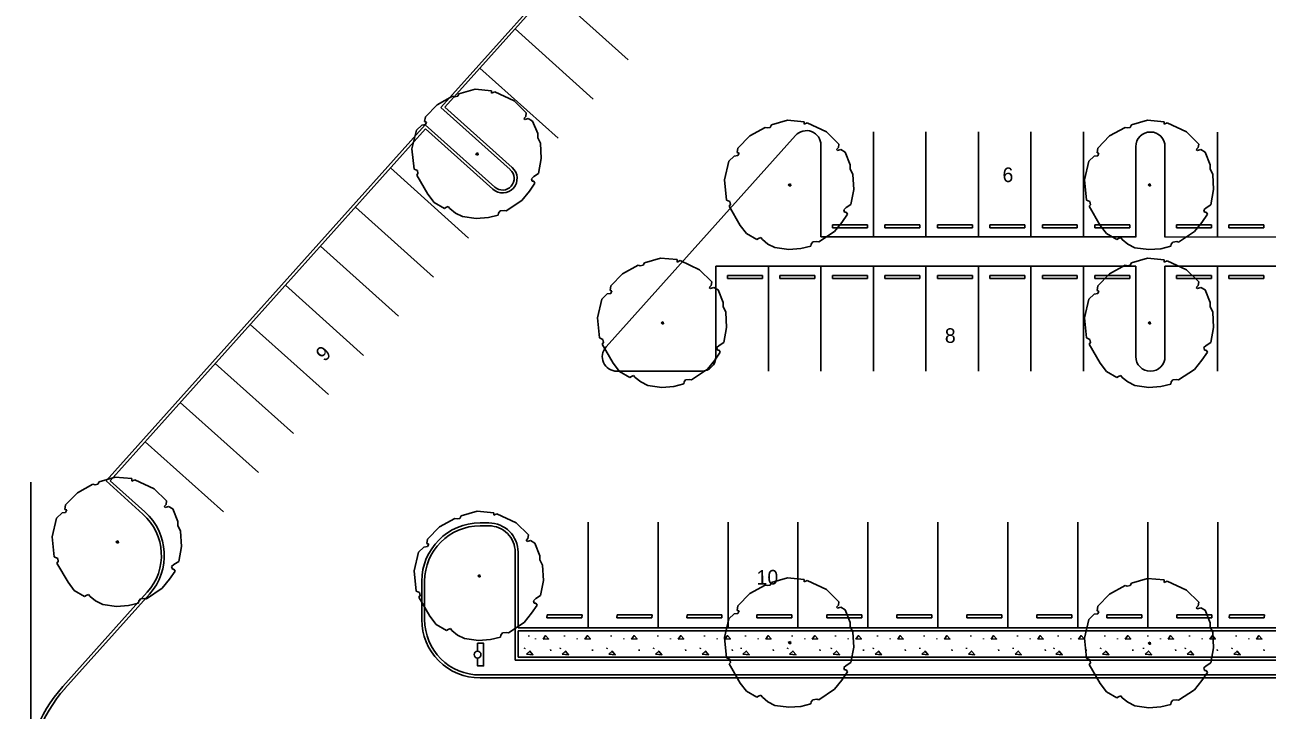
# Model space of a CAD drawing. Extents: x 6712138 to 6712574, y 1869536 to 1870160.
# Drawn here: x 6712157.5 to 6712370.5, y 1869919.6 to 1870037 of the extents above; entities that cross this region are included whole.
import ezdxf

# ---------------------------------------------------------------- set-up
doc = ezdxf.new("R2010")
doc.units = 0
for name, color, linetype in [('A-ANNO-TEXT', 7, 'Continuous'), ('A-FLOR-PATT', 7, 'Continuous'), ('C-Boun-Imaginary', 7, 'Continuous'), ('C-PRKG-CONC', 7, 'Continuous'), ('C-SIGN-PARKING', 7, 'Continuous'), ('L-tree', 7, 'Continuous')]:
    doc.layers.add(name, color=color, linetype=linetype)

# ---------------------------------------------------------------- blocks, each defined once
blk = doc.blocks.new('TREE 1')
at = {"layer": 'L-tree'}
for p, q in [((-0.027, 0.572), (-0.168, 0.532)), ((0.117, 0.559), (-0.027, 0.572)), ((0.117, 0.537), (0.117, 0.559)), ((0.144, 0.55), (0.117, 0.537)), ((0.312, 0.471), (0.144, 0.55)), ((-0.357, 0.436), (-0.46, 0.33)), ((-0.223, 0.51), (-0.357, 0.436)), ((-0.203, 0.506), (-0.223, 0.51)), ((-0.178, 0.51), (-0.203, 0.506)), ((-0.168, 0.532), (-0.178, 0.51)), ((0.419, 0.365), (0.312, 0.471)), ((-0.46, 0.33), (-0.467, 0.29)), ((0.398, 0.317), (0.415, 0.334)), ((0.415, 0.334), (0.419, 0.365)), ((-0.491, 0.26), (-0.539, 0.216)), ((-0.46, 0.264), (-0.491, 0.26)), ((-0.467, 0.29), (-0.45, 0.286)), ((-0.45, 0.286), (-0.46, 0.264)), ((0.408, 0.308), (0.398, 0.317)), ((0.436, 0.317), (0.408, 0.308)), ((0.474, 0.295), (0.436, 0.317)), ((0.518, 0.185), (0.474, 0.295)), ((-0.539, 0.216), (-0.577, 0.053)), ((0.518, 0.15), (0.518, 0.185)), ((0.542, 0.101), (0.518, 0.15)), ((-0.577, 0.053), (-0.559, -0.123)), ((-0.003, 0.018), (-0.021, 0.009)), ((-0.021, 0.009), (-0.014, 0)), ((-0.014, 0), (0, 0)), ((0, 0), (-0.003, 0.018)), ((0.549, -0.031), (0.542, 0.101)), ((0.525, -0.163), (0.549, -0.031)), ((-0.559, -0.123), (-0.529, -0.136)), ((-0.525, -0.163), (-0.535, -0.176)), ((-0.535, -0.176), (-0.439, -0.343)), ((-0.529, -0.136), (-0.525, -0.163)), ((0.463, -0.207), (0.484, -0.189)), ((0.47, -0.229), (0.463, -0.207)), ((0.484, -0.189), (0.525, -0.163)), ((0.381, -0.396), (0.446, -0.317)), ((0.446, -0.317), (0.494, -0.246)), ((0.484, -0.229), (0.47, -0.229)), ((0.494, -0.246), (0.484, -0.229)), ((-0.439, -0.343), (-0.384, -0.414)), ((-0.384, -0.414), (-0.295, -0.466)), ((0.244, -0.488), (0.381, -0.396)), ((-0.295, -0.466), (-0.281, -0.458)), ((-0.281, -0.458), (-0.261, -0.449)), ((-0.261, -0.449), (-0.247, -0.466)), ((-0.247, -0.466), (-0.199, -0.506)), ((-0.199, -0.506), (-0.137, -0.537)), ((-0.137, -0.537), (-0.017, -0.554)), ((0.089, -0.546), (0.175, -0.524)), ((0.175, -0.524), (0.178, -0.506)), ((0.178, -0.506), (0.192, -0.488)), ((0.192, -0.488), (0.227, -0.484)), ((0.227, -0.484), (0.244, -0.488)), ((-0.017, -0.554), (0.089, -0.546))]:
    blk.add_line(p, q, dxfattribs=at)

msp = doc.modelspace()

# ---------------------------------------------------------------- linework, layer by layer
at = {"layer": 'A-FLOR-PATT'}
for p, q in [((6712243.93, 1869932.21), (6712243.93, 1869932.37)), ((6712245.05, 1869931.74), (6712245.05, 1869931.85)), ((6712250.04, 1869932.21), (6712250.04, 1869932.37)), ((6712252.21, 1869931.74), (6712252.21, 1869931.85)), ((6712258.04, 1869932.21), (6712258.04, 1869932.37)), ((6712260.21, 1869931.74), (6712260.21, 1869931.85)), ((6712266.04, 1869932.21), (6712266.04, 1869932.37)), ((6712268.21, 1869931.74), (6712268.21, 1869931.85)), ((6712274.04, 1869932.21), (6712274.04, 1869932.37)), ((6712276.21, 1869931.74), (6712276.21, 1869931.85)), ((6712281.04, 1869932.21), (6712281.04, 1869932.37)), ((6712283.21, 1869931.74), (6712283.21, 1869931.85)), ((6712289.04, 1869932.21), (6712289.04, 1869932.37)), ((6712291.21, 1869931.74), (6712291.21, 1869931.85)), ((6712296.52, 1869932.21), (6712296.52, 1869932.37)), ((6712298.69, 1869931.74), (6712298.69, 1869931.85)), ((6712303.69, 1869932.21), (6712303.69, 1869932.37)), ((6712305.86, 1869931.74), (6712305.86, 1869931.85)), ((6712311.69, 1869932.21), (6712311.69, 1869932.37)), ((6712313.86, 1869931.74), (6712313.86, 1869931.85)), ((6712319.69, 1869932.21), (6712319.69, 1869932.37)), ((6712321.86, 1869931.74), (6712321.86, 1869931.85)), ((6712327.69, 1869932.21), (6712327.69, 1869932.37)), ((6712329.86, 1869931.74), (6712329.86, 1869931.85)), ((6712334.69, 1869932.21), (6712334.69, 1869932.37)), ((6712336.86, 1869931.74), (6712336.86, 1869931.85)), ((6712342.69, 1869932.21), (6712342.69, 1869932.37)), ((6712344.86, 1869931.74), (6712344.86, 1869931.85)), ((6712350.04, 1869932.21), (6712350.04, 1869932.37)), ((6712352.21, 1869931.74), (6712352.21, 1869931.85)), ((6712357.2, 1869932.21), (6712357.2, 1869932.37)), ((6712359.37, 1869931.74), (6712359.37, 1869931.85)), ((6712365.2, 1869932.21), (6712365.2, 1869932.37)), ((6712367.37, 1869931.74), (6712367.37, 1869931.85)), ((6712243.18, 1869930.12), (6712243.22, 1869930.24)), ((6712247.68, 1869929.77), (6712247.64, 1869929.97)), ((6712249.29, 1869930.12), (6712249.33, 1869930.24)), ((6712254.84, 1869929.77), (6712254.8, 1869929.97)), ((6712257.29, 1869930.12), (6712257.33, 1869930.24)), ((6712262.84, 1869929.77), (6712262.8, 1869929.97)), ((6712265.29, 1869930.12), (6712265.33, 1869930.24)), ((6712270.84, 1869929.77), (6712270.8, 1869929.97)), ((6712273.29, 1869930.12), (6712273.33, 1869930.24)), ((6712278.84, 1869929.77), (6712278.8, 1869929.97)), ((6712280.29, 1869930.12), (6712280.33, 1869930.24)), ((6712285.84, 1869929.77), (6712285.8, 1869929.97)), ((6712288.29, 1869930.12), (6712288.33, 1869930.24)), ((6712293.84, 1869929.77), (6712293.8, 1869929.97)), ((6712295.77, 1869930.12), (6712295.81, 1869930.24)), ((6712301.32, 1869929.77), (6712301.28, 1869929.97)), ((6712302.94, 1869930.12), (6712302.98, 1869930.24)), ((6712308.49, 1869929.77), (6712308.45, 1869929.97)), ((6712310.94, 1869930.12), (6712310.98, 1869930.24)), ((6712316.49, 1869929.77), (6712316.45, 1869929.97)), ((6712318.94, 1869930.12), (6712318.98, 1869930.24)), ((6712324.49, 1869929.77), (6712324.45, 1869929.97)), ((6712326.94, 1869930.12), (6712326.98, 1869930.24)), ((6712332.49, 1869929.77), (6712332.45, 1869929.97)), ((6712333.94, 1869930.12), (6712333.98, 1869930.24)), ((6712339.49, 1869929.77), (6712339.45, 1869929.97)), ((6712341.94, 1869930.12), (6712341.98, 1869930.24)), ((6712347.49, 1869929.77), (6712347.45, 1869929.97)), ((6712349.29, 1869930.12), (6712349.33, 1869930.24)), ((6712354.84, 1869929.77), (6712354.8, 1869929.97)), ((6712356.45, 1869930.12), (6712356.49, 1869930.24)), ((6712362, 1869929.77), (6712361.96, 1869929.97)), ((6712364.45, 1869930.12), (6712364.49, 1869930.24)), ((6712370, 1869929.77), (6712369.96, 1869929.97))]:
    msp.add_line(p, q, dxfattribs=at)
for points in [[(6712246.36, 1869931.74), (6712246.79, 1869932.37), (6712247.3, 1869931.78)], [(6712253.52, 1869931.74), (6712253.95, 1869932.37), (6712254.46, 1869931.78)], [(6712261.52, 1869931.74), (6712261.95, 1869932.37), (6712262.46, 1869931.78)], [(6712269.52, 1869931.74), (6712269.95, 1869932.37), (6712270.46, 1869931.78)], [(6712277.52, 1869931.74), (6712277.95, 1869932.37), (6712278.46, 1869931.78)], [(6712284.52, 1869931.74), (6712284.95, 1869932.37), (6712285.46, 1869931.78)], [(6712292.52, 1869931.74), (6712292.95, 1869932.37), (6712293.46, 1869931.78)], [(6712300, 1869931.74), (6712300.43, 1869932.37), (6712300.94, 1869931.78)], [(6712307.17, 1869931.74), (6712307.6, 1869932.37), (6712308.11, 1869931.78)], [(6712315.17, 1869931.74), (6712315.6, 1869932.37), (6712316.11, 1869931.78)], [(6712323.17, 1869931.74), (6712323.6, 1869932.37), (6712324.11, 1869931.78)], [(6712331.17, 1869931.74), (6712331.6, 1869932.37), (6712332.11, 1869931.78)], [(6712338.17, 1869931.74), (6712338.6, 1869932.37), (6712339.11, 1869931.78)], [(6712346.17, 1869931.74), (6712346.6, 1869932.37), (6712347.11, 1869931.78)], [(6712353.52, 1869931.74), (6712353.95, 1869932.37), (6712354.46, 1869931.78)], [(6712360.68, 1869931.74), (6712361.11, 1869932.37), (6712361.62, 1869931.78)], [(6712368.68, 1869931.74), (6712369.11, 1869932.37), (6712369.62, 1869931.78)], [(6712243.52, 1869929.16), (6712244.08, 1869929.71), (6712244.62, 1869929.08)], [(6712249.63, 1869929.16), (6712250.19, 1869929.71), (6712250.73, 1869929.08)], [(6712257.63, 1869929.16), (6712258.19, 1869929.71), (6712258.73, 1869929.08)], [(6712265.63, 1869929.16), (6712266.19, 1869929.71), (6712266.73, 1869929.08)], [(6712273.63, 1869929.16), (6712274.19, 1869929.71), (6712274.73, 1869929.08)], [(6712280.63, 1869929.16), (6712281.19, 1869929.71), (6712281.73, 1869929.08)], [(6712288.63, 1869929.16), (6712289.19, 1869929.71), (6712289.73, 1869929.08)], [(6712296.11, 1869929.16), (6712296.67, 1869929.71), (6712297.21, 1869929.08)], [(6712303.28, 1869929.16), (6712303.84, 1869929.71), (6712304.38, 1869929.08)], [(6712311.28, 1869929.16), (6712311.84, 1869929.71), (6712312.38, 1869929.08)], [(6712319.28, 1869929.16), (6712319.84, 1869929.71), (6712320.38, 1869929.08)], [(6712327.28, 1869929.16), (6712327.84, 1869929.71), (6712328.38, 1869929.08)], [(6712334.28, 1869929.16), (6712334.84, 1869929.71), (6712335.38, 1869929.08)], [(6712342.28, 1869929.16), (6712342.84, 1869929.71), (6712343.38, 1869929.08)], [(6712349.62, 1869929.16), (6712350.18, 1869929.71), (6712350.72, 1869929.08)], [(6712356.79, 1869929.16), (6712357.35, 1869929.71), (6712357.89, 1869929.08)], [(6712364.79, 1869929.16), (6712365.35, 1869929.71), (6712365.89, 1869929.08)]]:
    msp.add_lwpolyline(points, close=True, dxfattribs=at)
at = {"layer": 'C-Boun-Imaginary'}
msp.add_lwpolyline([(6712158.49, 1869958.67), (6712158.49, 1869788.19), (6712188.82, 1869788.19)], dxfattribs=at)
at = {"layer": 'C-PRKG-CONC'}
for p, q in [((6712228.82, 1870022.9), (6712283.55, 1870083.96)), ((6712229.52, 1870022.94), (6712283.59, 1870083.26)), ((6712247.54, 1870043.05), (6712260.95, 1870031.03)), ((6712241.54, 1870036.34), (6712254.94, 1870024.33)), ((6712235.53, 1870029.64), (6712248.93, 1870017.63)), ((6712228.82, 1870022.9), (6712240.73, 1870012.22)), ((6712229.52, 1870022.94), (6712241.07, 1870012.59)), ((6712226.15, 1870019.92), (6712171.42, 1869958.86)), ((6712226.19, 1870019.22), (6712172.12, 1869958.9)), ((6712238.06, 1870009.24), (6712226.15, 1870019.92)), ((6712237.73, 1870008.87), (6712226.19, 1870019.22)), ((6712302.99, 1870000.68), (6712302.99, 1870018.68)), ((6712311.99, 1870000.68), (6712311.99, 1870018.68)), ((6712320.99, 1870000.68), (6712320.99, 1870018.68)), ((6712329.99, 1870000.68), (6712329.99, 1870018.68)), ((6712338.99, 1870000.68), (6712338.99, 1870018.68)), ((6712361.99, 1870000.67), (6712361.99, 1870018.67)), ((6712257.14, 1869981.84), (6712289.63, 1870018.08)), ((6712293.99, 1870016.41), (6712293.99, 1870000.68)), ((6712347.99, 1870016.17), (6712347.99, 1870000.67)), ((6712352.99, 1870016.17), (6712352.99, 1870000.67)), ((6712220.18, 1870012.51), (6712233.58, 1870000.5)), ((6712214.17, 1870005.81), (6712227.58, 1869993.8)), ((6712295.96, 1870002.26), (6712295.96, 1870002.76)), ((6712295.96, 1870002.76), (6712301.96, 1870002.76)), ((6712301.96, 1870002.26), (6712295.96, 1870002.26)), ((6712301.96, 1870002.76), (6712301.96, 1870002.26)), ((6712304.96, 1870002.26), (6712304.96, 1870002.76)), ((6712304.96, 1870002.76), (6712310.96, 1870002.76)), ((6712310.96, 1870002.26), (6712304.96, 1870002.26)), ((6712310.96, 1870002.76), (6712310.96, 1870002.26)), ((6712313.96, 1870002.26), (6712313.96, 1870002.76)), ((6712313.96, 1870002.76), (6712319.96, 1870002.76)), ((6712319.96, 1870002.26), (6712313.96, 1870002.26)), ((6712319.96, 1870002.76), (6712319.96, 1870002.26)), ((6712322.96, 1870002.26), (6712322.96, 1870002.76)), ((6712322.96, 1870002.76), (6712328.96, 1870002.76)), ((6712328.96, 1870002.26), (6712322.96, 1870002.26)), ((6712328.96, 1870002.76), (6712328.96, 1870002.26)), ((6712331.96, 1870002.26), (6712331.96, 1870002.76)), ((6712331.96, 1870002.76), (6712337.96, 1870002.76)), ((6712337.96, 1870002.26), (6712331.96, 1870002.26)), ((6712337.96, 1870002.76), (6712337.96, 1870002.26)), ((6712340.96, 1870002.26), (6712340.96, 1870002.76)), ((6712340.96, 1870002.76), (6712346.96, 1870002.76)), ((6712346.96, 1870002.26), (6712340.96, 1870002.26)), ((6712346.96, 1870002.76), (6712346.96, 1870002.26)), ((6712354.96, 1870002.26), (6712354.96, 1870002.76)), ((6712354.96, 1870002.76), (6712360.96, 1870002.76)), ((6712360.96, 1870002.26), (6712354.96, 1870002.26)), ((6712360.96, 1870002.76), (6712360.96, 1870002.26)), ((6712363.96, 1870002.26), (6712363.96, 1870002.76)), ((6712363.96, 1870002.76), (6712369.96, 1870002.76)), ((6712369.96, 1870002.26), (6712363.96, 1870002.26)), ((6712369.96, 1870002.76), (6712369.96, 1870002.26)), ((6712208.17, 1869999.11), (6712221.57, 1869987.1)), ((6712293.99, 1870000.68), (6712347.99, 1870000.68)), ((6712352.99, 1870000.68), (6712397.99, 1870000.67)), ((6712275.99, 1869995.68), (6712347.99, 1869995.67)), ((6712275.99, 1869980.17), (6712275.99, 1869995.68)), ((6712284.99, 1869995.67), (6712284.99, 1869977.67)), ((6712293.99, 1869995.67), (6712293.99, 1869977.67)), ((6712302.99, 1869995.67), (6712302.99, 1869977.67)), ((6712311.99, 1869995.67), (6712311.99, 1869977.67)), ((6712320.99, 1869995.67), (6712320.99, 1869977.67)), ((6712329.99, 1869995.67), (6712329.99, 1869977.67)), ((6712338.99, 1869995.67), (6712338.99, 1869977.67)), ((6712347.99, 1869980.17), (6712347.99, 1869995.67)), ((6712352.99, 1869995.67), (6712397.99, 1869995.67)), ((6712352.99, 1869980.17), (6712352.99, 1869995.67)), ((6712361.99, 1869995.67), (6712361.99, 1869977.67)), ((6712277.96, 1869994.09), (6712277.96, 1869993.59)), ((6712283.96, 1869994.09), (6712277.96, 1869994.09)), ((6712277.96, 1869993.59), (6712283.96, 1869993.59)), ((6712283.96, 1869993.59), (6712283.96, 1869994.09)), ((6712286.96, 1869994.09), (6712286.96, 1869993.59)), ((6712292.96, 1869994.09), (6712286.96, 1869994.09)), ((6712286.96, 1869993.59), (6712292.96, 1869993.59)), ((6712292.96, 1869993.59), (6712292.96, 1869994.09)), ((6712295.96, 1869994.09), (6712295.96, 1869993.59)), ((6712301.96, 1869994.09), (6712295.96, 1869994.09)), ((6712295.96, 1869993.59), (6712301.96, 1869993.59)), ((6712301.96, 1869993.59), (6712301.96, 1869994.09)), ((6712304.96, 1869994.09), (6712304.96, 1869993.59)), ((6712310.96, 1869994.09), (6712304.96, 1869994.09)), ((6712304.96, 1869993.59), (6712310.96, 1869993.59)), ((6712310.96, 1869993.59), (6712310.96, 1869994.09)), ((6712313.96, 1869994.09), (6712313.96, 1869993.59)), ((6712319.96, 1869994.09), (6712313.96, 1869994.09)), ((6712313.96, 1869993.59), (6712319.96, 1869993.59)), ((6712319.96, 1869993.59), (6712319.96, 1869994.09)), ((6712322.96, 1869994.09), (6712322.96, 1869993.59)), ((6712328.96, 1869994.09), (6712322.96, 1869994.09)), ((6712322.96, 1869993.59), (6712328.96, 1869993.59)), ((6712328.96, 1869993.59), (6712328.96, 1869994.09)), ((6712331.96, 1869994.09), (6712331.96, 1869993.59)), ((6712337.96, 1869994.09), (6712331.96, 1869994.09)), ((6712331.96, 1869993.59), (6712337.96, 1869993.59)), ((6712337.96, 1869993.59), (6712337.96, 1869994.09)), ((6712340.96, 1869994.09), (6712340.96, 1869993.59)), ((6712346.96, 1869994.09), (6712340.96, 1869994.09)), ((6712340.96, 1869993.59), (6712346.96, 1869993.59)), ((6712346.96, 1869993.59), (6712346.96, 1869994.09)), ((6712354.96, 1869994.09), (6712354.96, 1869993.59)), ((6712360.96, 1869994.09), (6712354.96, 1869994.09)), ((6712354.96, 1869993.59), (6712360.96, 1869993.59)), ((6712360.96, 1869993.59), (6712360.96, 1869994.09)), ((6712363.96, 1869994.09), (6712363.96, 1869993.59)), ((6712369.96, 1869994.09), (6712363.96, 1869994.09)), ((6712363.96, 1869993.59), (6712369.96, 1869993.59)), ((6712369.96, 1869993.59), (6712369.96, 1869994.09)), ((6712202.16, 1869992.41), (6712215.56, 1869980.39)), ((6712196.15, 1869985.71), (6712209.55, 1869973.69)), ((6712190.14, 1869979.01), (6712203.55, 1869966.99)), ((6712273.49, 1869977.67), (6712259.01, 1869977.67)), ((6712184.14, 1869972.3), (6712197.54, 1869960.29)), ((6712178.13, 1869965.6), (6712191.53, 1869953.59)), ((6712171.42, 1869958.86), (6712177.74, 1869953.19)), ((6712172.12, 1869958.9), (6712178.08, 1869953.56)), ((6712235.54, 1869951.67), (6712237.06, 1869951.67)), ((6712235.54, 1869951.17), (6712237.06, 1869951.17)), ((6712254.06, 1869951.82), (6712254.06, 1869933.82)), ((6712266.06, 1869951.82), (6712266.06, 1869933.82)), ((6712278.06, 1869951.82), (6712278.06, 1869933.82)), ((6712290.06, 1869951.82), (6712290.06, 1869933.82)), ((6712302.06, 1869951.82), (6712302.06, 1869933.82)), ((6712314.06, 1869951.82), (6712314.06, 1869933.82)), ((6712326.06, 1869951.82), (6712326.06, 1869933.82)), ((6712338.06, 1869951.82), (6712338.06, 1869933.82)), ((6712350.06, 1869951.82), (6712350.06, 1869933.82)), ((6712362.06, 1869951.82), (6712362.06, 1869933.82)), ((6712362.06, 1869951.82), (6712362.06, 1869933.82)), ((6712241.56, 1869946.67), (6712241.56, 1869928.17)), ((6712242.06, 1869946.67), (6712242.06, 1869933.67)), ((6712225.54, 1869941.67), (6712225.54, 1869935.11)), ((6712226.04, 1869941.67), (6712226.04, 1869935.11)), ((6712178.48, 1869939.78), (6712164, 1869923.62)), ((6712178.85, 1869939.44), (6712164.37, 1869923.29)), ((6712247.02, 1869935.41), (6712247.03, 1869935.91)), ((6712247.02, 1869935.41), (6712247.03, 1869935.91)), ((6712253.02, 1869935.41), (6712247.02, 1869935.41)), ((6712253.02, 1869935.41), (6712247.02, 1869935.41)), ((6712247.03, 1869935.91), (6712253.03, 1869935.91)), ((6712247.03, 1869935.91), (6712253.03, 1869935.91)), ((6712253.03, 1869935.91), (6712253.02, 1869935.41)), ((6712253.03, 1869935.91), (6712253.02, 1869935.41)), ((6712259.02, 1869935.41), (6712259.03, 1869935.91)), ((6712265.02, 1869935.41), (6712259.02, 1869935.41)), ((6712259.03, 1869935.91), (6712265.03, 1869935.91)), ((6712265.03, 1869935.91), (6712265.02, 1869935.41)), ((6712271.02, 1869935.41), (6712271.03, 1869935.91)), ((6712277.02, 1869935.41), (6712271.02, 1869935.41)), ((6712271.03, 1869935.91), (6712277.03, 1869935.91)), ((6712277.03, 1869935.91), (6712277.02, 1869935.41)), ((6712283.02, 1869935.41), (6712283.03, 1869935.91)), ((6712289.02, 1869935.41), (6712283.02, 1869935.41)), ((6712283.03, 1869935.91), (6712289.03, 1869935.91)), ((6712289.03, 1869935.91), (6712289.02, 1869935.41)), ((6712295.02, 1869935.41), (6712295.03, 1869935.91)), ((6712301.02, 1869935.41), (6712295.02, 1869935.41)), ((6712295.03, 1869935.91), (6712301.03, 1869935.91)), ((6712301.03, 1869935.91), (6712301.02, 1869935.41)), ((6712307.02, 1869935.41), (6712307.03, 1869935.91)), ((6712313.02, 1869935.41), (6712307.02, 1869935.41)), ((6712307.03, 1869935.91), (6712313.03, 1869935.91)), ((6712313.03, 1869935.91), (6712313.02, 1869935.41)), ((6712319.02, 1869935.41), (6712319.03, 1869935.91)), ((6712325.02, 1869935.41), (6712319.02, 1869935.41)), ((6712319.03, 1869935.91), (6712325.03, 1869935.91)), ((6712325.03, 1869935.91), (6712325.02, 1869935.41)), ((6712331.02, 1869935.41), (6712331.03, 1869935.91)), ((6712337.02, 1869935.41), (6712331.02, 1869935.41)), ((6712331.03, 1869935.91), (6712337.03, 1869935.91)), ((6712337.03, 1869935.91), (6712337.02, 1869935.41)), ((6712343.02, 1869935.41), (6712343.03, 1869935.91)), ((6712349.02, 1869935.41), (6712343.02, 1869935.41)), ((6712343.03, 1869935.91), (6712349.03, 1869935.91)), ((6712349.03, 1869935.91), (6712349.02, 1869935.41)), ((6712355.02, 1869935.41), (6712355.03, 1869935.91)), ((6712355.02, 1869935.41), (6712355.03, 1869935.91)), ((6712361.02, 1869935.41), (6712355.02, 1869935.41)), ((6712361.02, 1869935.41), (6712355.02, 1869935.41)), ((6712355.03, 1869935.91), (6712361.03, 1869935.91)), ((6712355.03, 1869935.91), (6712361.03, 1869935.91)), ((6712361.03, 1869935.91), (6712361.02, 1869935.41)), ((6712361.03, 1869935.91), (6712361.02, 1869935.41)), ((6712364.02, 1869935.41), (6712364.03, 1869935.91)), ((6712370.02, 1869935.41), (6712364.02, 1869935.41)), ((6712364.03, 1869935.91), (6712370.03, 1869935.91)), ((6712370.03, 1869935.91), (6712370.02, 1869935.41)), ((6712242.06, 1869933.67), (6712471.06, 1869933.67)), ((6712242.06, 1869933.17), (6712242.06, 1869928.67)), ((6712242.06, 1869933.17), (6712470.56, 1869933.17)), ((6712241.56, 1869928.17), (6712470.56, 1869928.17)), ((6712242.06, 1869928.67), (6712470.56, 1869928.67)), ((6712470.56, 1869925.61), (6712235.54, 1869925.61)), ((6712471.06, 1869925.11), (6712235.54, 1869925.11))]:
    msp.add_line(p, q, dxfattribs=at)
for centre, radius, start, end in [((6712291.49, 1870016.41), 2.5, 360, 138.1293), ((6712350.49, 1870016.17), 2.5, 0, 180), ((6712239.4, 1870010.73), 2.5, 228.1293, 48.1293), ((6712239.4, 1870010.73), 2, 228.1293, 48.1293), ((6712259.01, 1869980.17), 2.5, 138.1293, 270), ((6712273.49, 1869980.17), 2.5, 270, 360), ((6712350.49, 1869980.17), 2.5, 180, 360), ((6712171.4, 1869946.12), 9.5, 318.1293, 48.1293), ((6712171.4, 1869946.12), 10, 318.1293, 48.1293), ((6712235.54, 1869941.67), 10, 90, 180), ((6712235.54, 1869941.67), 9.5, 90, 180), ((6712237.06, 1869946.67), 5, 359.9997, 90.0093), ((6712237.06, 1869946.67), 4.5, 359.9997, 90.0093), ((6712235.54, 1869935.11), 10, 180, 270.0004), ((6712235.54, 1869935.11), 9.5, 180, 270.0004), ((6712182.99, 1869906.6), 25.5, 138.1293, 180), ((6712182.99, 1869906.6), 25, 138.1293, 180)]:
    msp.add_arc(centre, radius, start, end, dxfattribs=at)
at = {"layer": 'C-SIGN-PARKING'}
msp.add_lwpolyline([(6712235.11, 1869929.69), (6712235.11, 1869931.04), (6712236.14, 1869931.04), (6712236.14, 1869927.16), (6712235.11, 1869927.16), (6712235.11, 1869928.51)], dxfattribs=at)
msp.add_circle((6712235.11, 1869929.1), 0.586, dxfattribs=at)

# ---------------------------------------------------------------- block references
at = {"layer": 'L-tree', "xscale": 19.68503937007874, "yscale": 19.68503937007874}
for p in [(6712235.23, 1870014.75), (6712288.81, 1870009.43), (6712350.53, 1870009.42), (6712267.02, 1869985.8), (6712350.53, 1869985.79), (6712173.53, 1869948.26), (6712235.59, 1869942.42), (6712288.81, 1869930.98), (6712350.53, 1869930.89)]:
    msp.add_blockref('TREE 1', p, dxfattribs=at)

# ---------------------------------------------------------------- texts
at = {"layer": 'A-ANNO-TEXT'}
for s, rotation, p in [('6', 0.2528, (6712325.13, 1870010.09)), ('8', 0.2528, (6712315.25, 1869982.53)), ('9', 45.2528, (6712208.89, 1869979.19)), ('10', 0.2528, (6712282.96, 1869941.11))]:
    msp.add_text(s, height=2.5, rotation=rotation, dxfattribs=at).set_placement(p)

doc.saveas('drawing.dxf')
